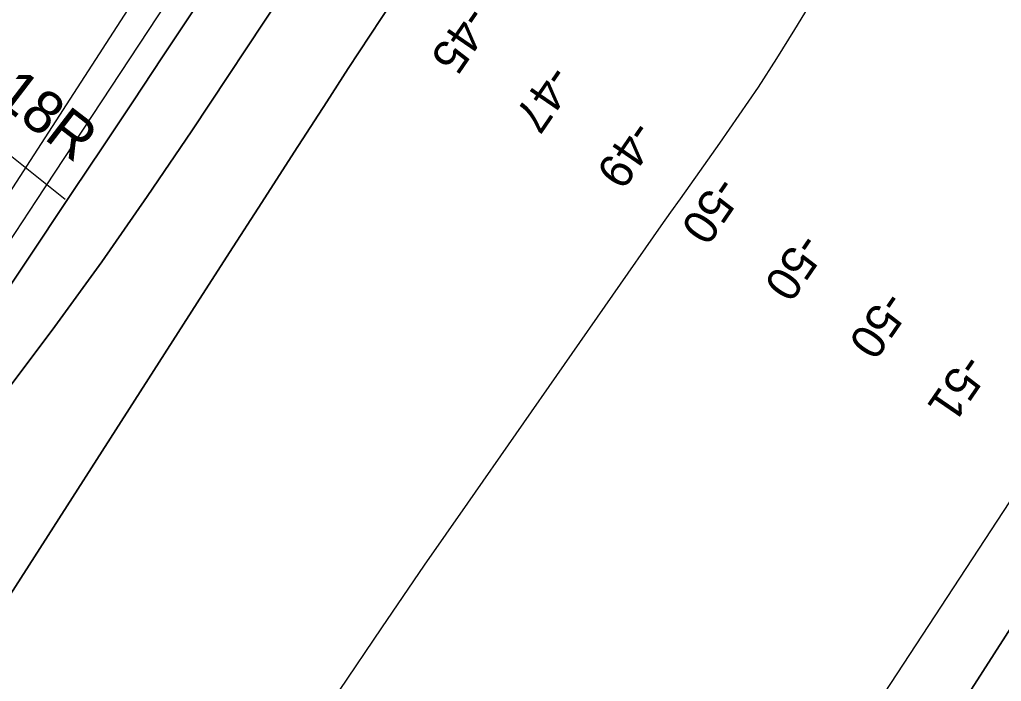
# Model space of a CAD drawing. Extents: x 3905714 to 3926767, y 183354 to 205755.
# Drawn here: x 3915542 to 3916511, y 191979 to 192631 of the extents above; entities that cross this region are included whole.
import ezdxf

# ---------------------------------------------------------------- set-up
doc = ezdxf.new("R2010")
doc.units = 0
for name, color, linetype in [('V-LEVE-TOET', 7, 'Continuous'), ('V-RIVR-RANG', 7, 'Continuous'), ('V-STRM-FMON', 7, 'Continuous'), ('V-TOPO-DPTH', 7, 'Continuous'), ('V-TOPO-MAJR', 7, 'Continuous'), ('V-TOPO-MINR', 7, 'Continuous')]:
    doc.layers.add(name, color=color, linetype=linetype)

msp = doc.modelspace()

# ---------------------------------------------------------------- linework, layer by layer
at = {"layer": 'V-LEVE-TOET'}
msp.add_lwpolyline([(3915587.35, 192453.97), (3915529.74, 192500.21), (3915491.27, 192519.73)], dxfattribs=at)
at = {"layer": 'V-TOPO-DPTH'}
for points in [[(3916071.24, 193295.95), (3916038.6, 193242.12), (3916005.79, 193188.39), (3915976.61, 193140.86), (3915958.09, 193111.09), (3915939.35, 193081.45), (3915920.28, 193052.03), (3915900.98, 193022.75), (3915881.52, 192993.58), (3915862.05, 192964.41), (3915842.58, 192935.24), (3915823.11, 192906.08), (3915766.82, 192821.76), (3915746.12, 192790.6), (3915725.5, 192759.39), (3915705.02, 192728.08), (3915684.62, 192696.72), (3915328.37, 192146.33)], [(3915354.77, 192101.61), (3915594.9, 192461.92), (3915624.41, 192506.19), (3915653.92, 192550.47), (3915683.44, 192594.74), (3915712.95, 192639.01), (3915761.89, 192712.4), (3915766.95, 192719.97), (3915772, 192727.54), (3915777.07, 192735.1), (3915782.14, 192742.65), (3915803.87, 192774.99), (3915819.73, 192798.77), (3915835.5, 192822.6), (3915851.13, 192846.53), (3915866.67, 192870.51), (3915967.26, 193026.84), (3915977.72, 193043.23), (3915988.09, 193059.68), (3915998.32, 193076.2), (3916008.47, 193092.79), (3916079.15, 193209.31), (3916124.67, 193284.13)], [(3916124.67, 193284.13), (3916079.15, 193209.31), (3916008.47, 193092.79), (3915998.32, 193076.2), (3915988.09, 193059.68), (3915977.72, 193043.23), (3915967.26, 193026.84), (3915866.67, 192870.51), (3915851.13, 192846.53), (3915835.5, 192822.6), (3915819.73, 192798.77), (3915803.87, 192774.99), (3915782.14, 192742.65), (3915777.07, 192735.1), (3915772, 192727.54), (3915766.95, 192719.97), (3915761.89, 192712.4), (3915712.95, 192639.01), (3915683.44, 192594.74), (3915653.92, 192550.47), (3915624.41, 192506.19), (3915594.9, 192461.92), (3915354.77, 192101.61)], [(3917061.2, 192872.63), (3916863.84, 192549.26), (3916848.3, 192524.17), (3916832.52, 192499.24), (3916816.39, 192474.53), (3916800.04, 192449.96), (3916720.6, 192332.42), (3916702.29, 192305.4), (3916683.94, 192278.42), (3916665.51, 192251.49), (3916647.03, 192224.59), (3916627.08, 192195.63), (3916618.6, 192183.19), (3916610.21, 192170.7), (3916601.94, 192158.13), (3916593.75, 192145.51), (3916213.51, 191553.05)], [(3917061.2, 192872.63), (3916863.84, 192549.26), (3916848.3, 192524.17), (3916832.52, 192499.24), (3916816.39, 192474.53), (3916800.04, 192449.96), (3916720.6, 192332.42), (3916702.29, 192305.4), (3916683.94, 192278.42), (3916665.51, 192251.49), (3916647.03, 192224.59), (3916627.08, 192195.63), (3916618.6, 192183.19), (3916610.21, 192170.7), (3916601.94, 192158.13), (3916593.75, 192145.51), (3916213.51, 191553.05)], [(3915909.88, 192649.15), (3915888.18, 192616.22), (3915866.64, 192583.19), (3915845.4, 192550.38), (3915813.39, 192500.85), (3915781.4, 192451.3), (3915749.48, 192401.71), (3915717.58, 192352.1), (3915495.1, 192005.58)], [(3915495.1, 192005.58), (3915717.58, 192352.1), (3915749.48, 192401.71), (3915781.4, 192451.3), (3915813.39, 192500.85), (3915845.4, 192550.38), (3915866.64, 192583.19), (3915888.18, 192616.22), (3915909.88, 192649.15)], [(3915530.12, 192266.08), (3915577.2, 192328.96), (3915623.41, 192392.47), (3915668.32, 192456.9), (3915712.36, 192521.95), (3915802.16, 192657.55)], [(3915530.12, 192266.08), (3915577.2, 192328.96), (3915623.41, 192392.47), (3915668.32, 192456.9), (3915712.36, 192521.95), (3915802.16, 192657.55)]]:
    msp.add_lwpolyline(points, dxfattribs=at)
at = {"layer": 'V-TOPO-MAJR'}
for points in [[(3916520.64, 193027.25), (3916491.77, 192968.32), (3916463.84, 192908.93), (3916428.17, 192830.68), (3916418.41, 192810.25), (3916408.17, 192790.06), (3916397.21, 192770.26), (3916385.77, 192750.71), (3916307.08, 192621.58), (3916289.3, 192593.11), (3916271.12, 192564.91), (3916252.34, 192537.12), (3916233.14, 192509.59), (3916213.22, 192481.67), (3916203.7, 192468.29), (3916194.21, 192454.89), (3916184.75, 192441.47), (3916175.32, 192428.02), (3915984.21, 192154.78), (3915941.68, 192093.42), (3915899.48, 192031.83), (3915857.8, 191969.9)], [(3916118.67, 191544.17), (3916525.89, 192165.5)]]:
    msp.add_lwpolyline(points, dxfattribs=at)
at = {"layer": 'V-TOPO-MINR'}
for points in [[(3916152.77, 193380.41), (3915975.7, 193081.51), (3915971.46, 193074.44), (3915967.17, 193067.4), (3915962.8, 193060.41), (3915958.39, 193053.45), (3915934.83, 193016.79), (3915918.49, 192991.6), (3915902, 192966.51), (3915885.28, 192941.57), (3915868.41, 192916.72), (3915775.16, 192780.66), (3915762.32, 192761.81), (3915749.55, 192742.92), (3915736.88, 192723.95), (3915724.29, 192704.93), (3915558.62, 192453.25), (3915516.92, 192389.85)], [(3916071.24, 193295.95), (3916038.6, 193242.12), (3916005.79, 193188.39), (3915976.61, 193140.86), (3915958.09, 193111.09), (3915939.35, 193081.45), (3915920.28, 193052.03), (3915900.98, 193022.75), (3915881.52, 192993.58), (3915862.05, 192964.41), (3915842.58, 192935.24), (3915823.11, 192906.08), (3915766.82, 192821.76), (3915746.12, 192790.6), (3915725.5, 192759.39), (3915705.02, 192728.08), (3915684.62, 192696.72), (3915328.37, 192146.33)], [(3916124.67, 193284.13), (3916079.15, 193209.31), (3916008.47, 193092.79), (3915998.32, 193076.2), (3915988.09, 193059.68), (3915977.72, 193043.23), (3915967.26, 193026.84), (3915866.67, 192870.51), (3915851.13, 192846.53), (3915835.5, 192822.6), (3915819.73, 192798.77), (3915803.87, 192774.99), (3915782.14, 192742.65), (3915777.07, 192735.1), (3915772, 192727.54), (3915766.95, 192719.97), (3915761.89, 192712.4), (3915712.95, 192639.01), (3915683.44, 192594.74), (3915653.92, 192550.47), (3915624.41, 192506.19), (3915594.9, 192461.92), (3915354.77, 192101.61)], [(3916213.51, 191553.05), (3916593.75, 192145.51), (3916601.94, 192158.13), (3916610.21, 192170.7), (3916618.6, 192183.19), (3916627.08, 192195.63), (3916647.03, 192224.59), (3916665.51, 192251.49), (3916683.94, 192278.42), (3916702.29, 192305.4), (3916720.6, 192332.42), (3916800.04, 192449.96), (3916816.39, 192474.53), (3916832.52, 192499.24), (3916848.3, 192524.17), (3916863.84, 192549.26), (3917061.2, 192872.63)], [(3915909.88, 192649.15), (3915888.18, 192616.22), (3915866.64, 192583.19), (3915845.4, 192550.38), (3915813.39, 192500.85), (3915781.4, 192451.3), (3915749.48, 192401.71), (3915717.58, 192352.1), (3915495.1, 192005.58)], [(3915802.16, 192657.55), (3915712.36, 192521.95), (3915668.32, 192456.9), (3915623.41, 192392.47), (3915577.2, 192328.96), (3915530.12, 192266.08)]]:
    msp.add_lwpolyline(points, dxfattribs=at)

# ---------------------------------------------------------------- texts
at = {"layer": 'V-RIVR-RANG'}
for s, p in [('-45', (3915983.38, 192647.35)), ('-47', (3916065.16, 192589.25)), ('-49', (3916146.92, 192534.5)), ('-50', (3916230.39, 192479.39)), ('-50', (3916312.46, 192423.32)), ('-50', (3916395.94, 192366.29)), ('-51', (3916473.76, 192304.18))]:
    msp.add_text(s, height=33.5, rotation=235.60042, dxfattribs=at).set_placement(p)
at = {"layer": 'V-STRM-FMON'}
msp.add_text('11.18R', height=42, rotation=322.47424, dxfattribs=at).set_placement((3915453.89, 192599.95))

doc.saveas('drawing.dxf')
